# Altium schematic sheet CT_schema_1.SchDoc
size 404 x 338 mm
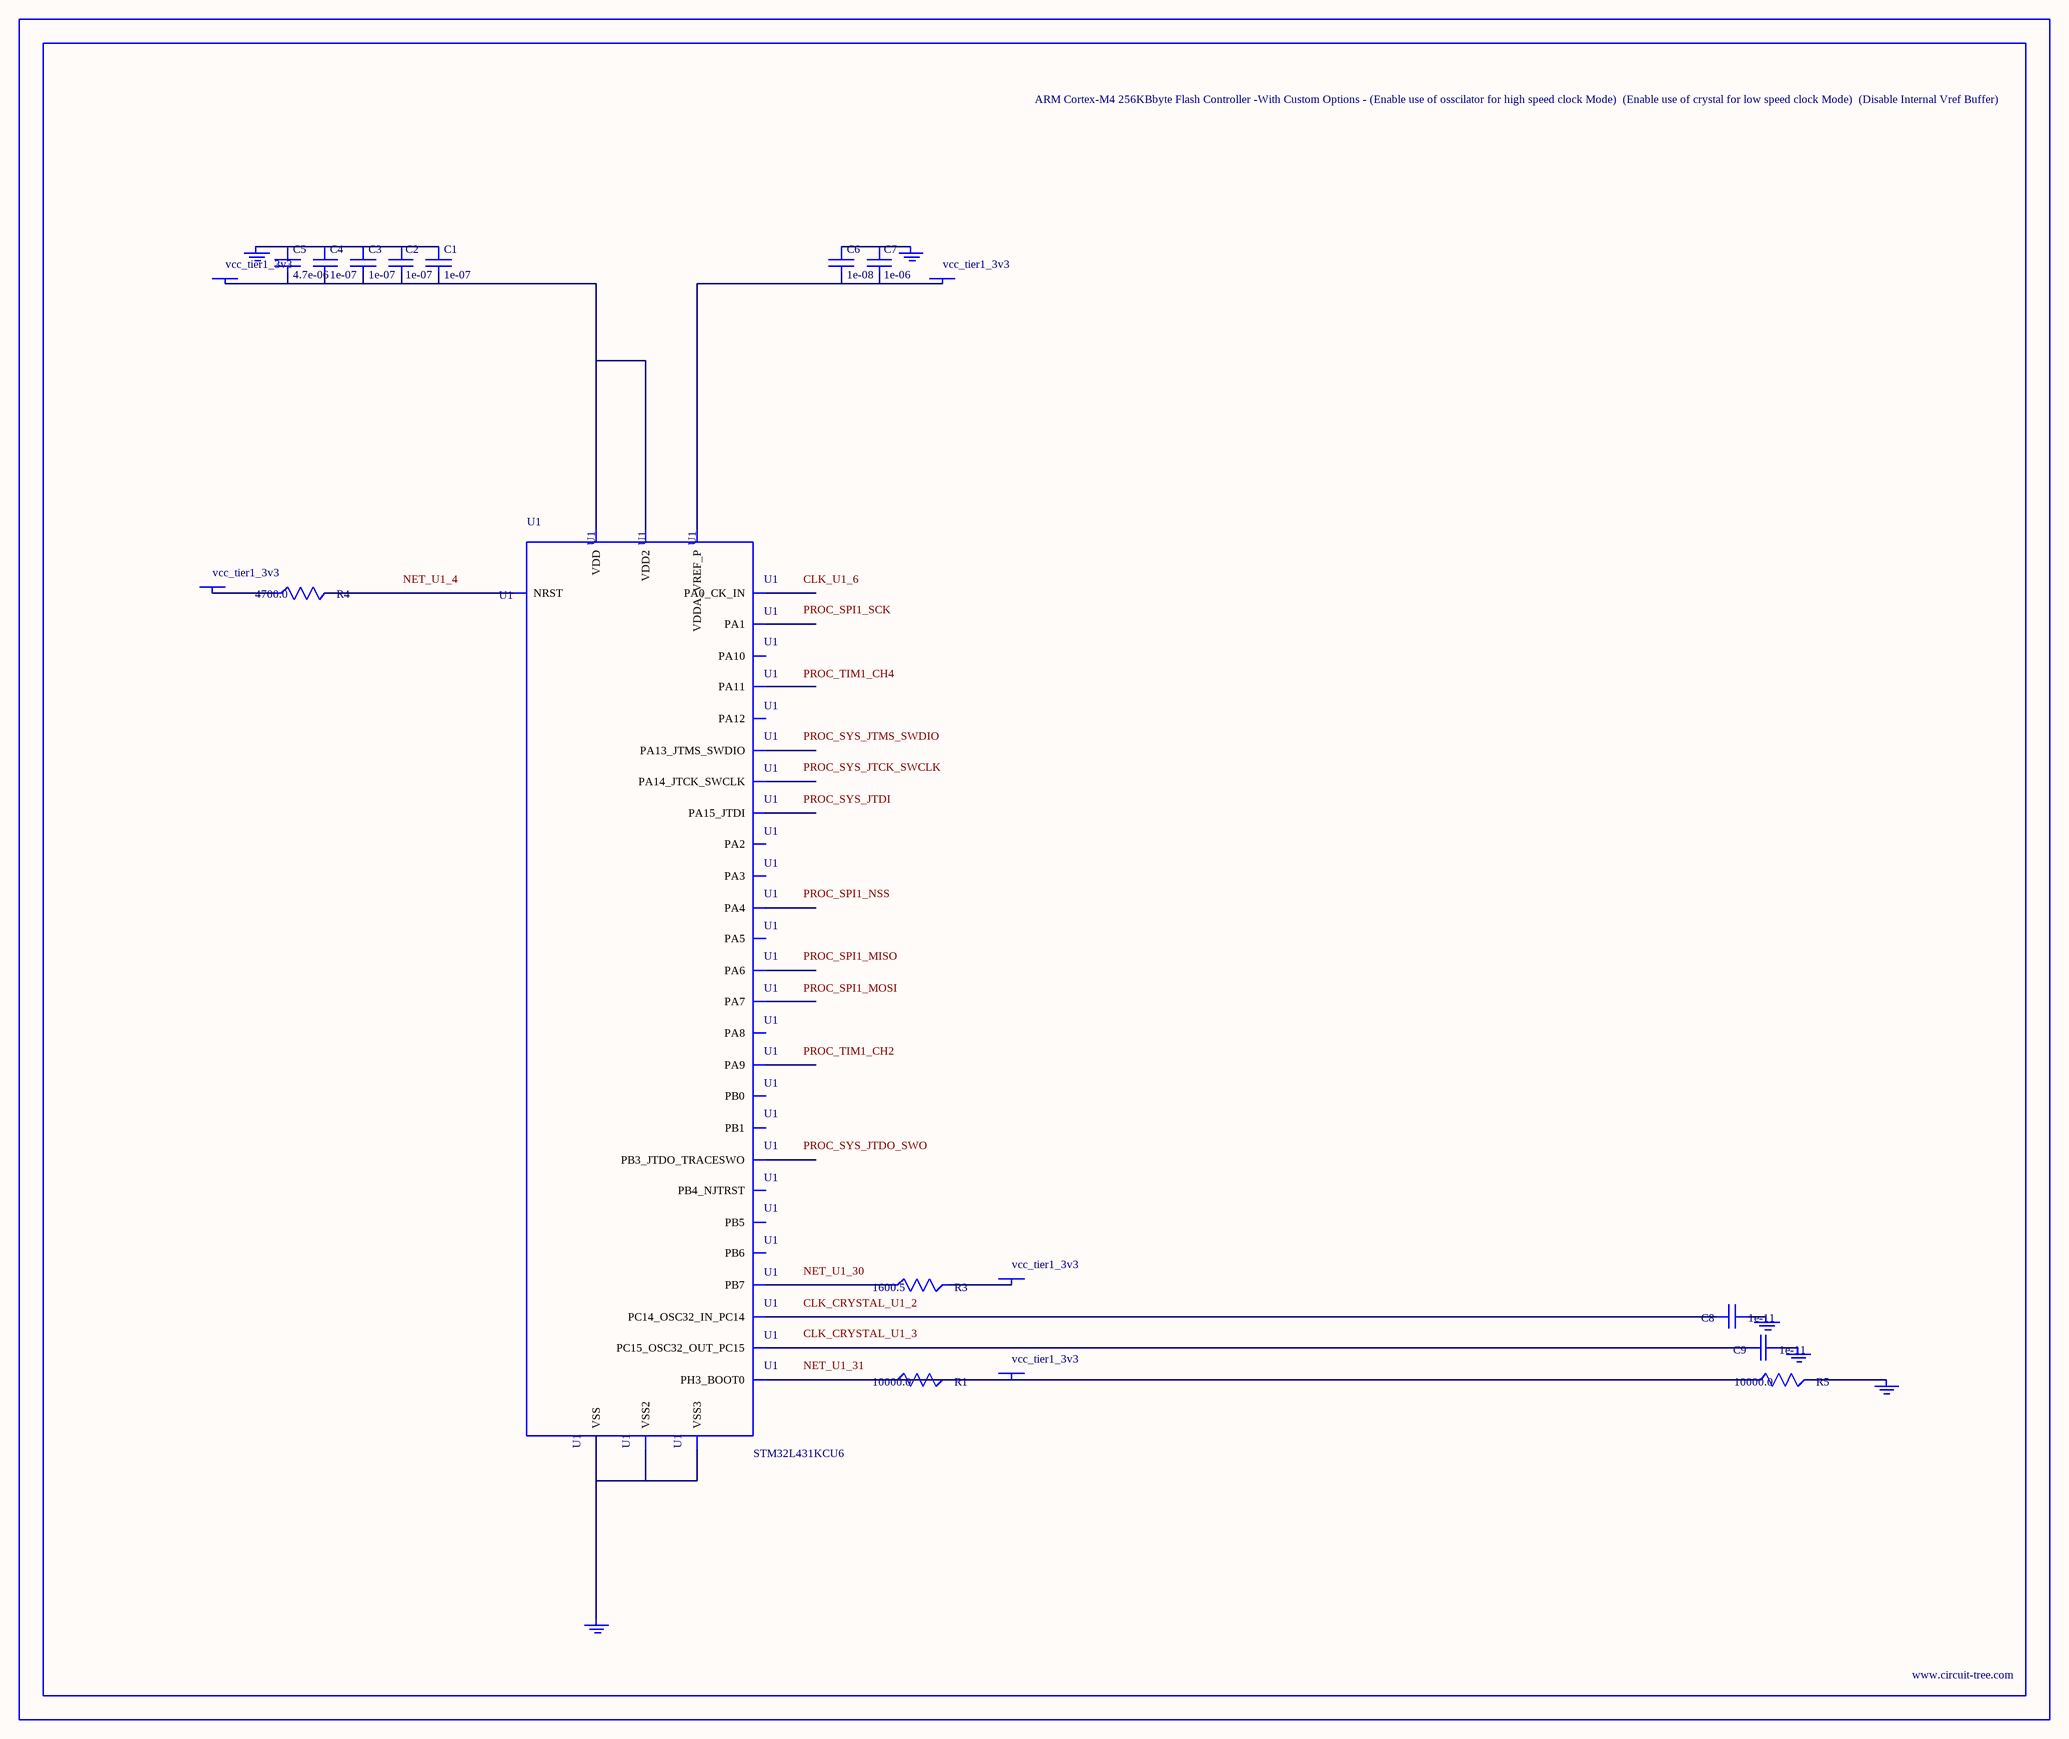
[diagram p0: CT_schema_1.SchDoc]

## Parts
BORDER0  (no value)
C1  1e-07  [C0603]
C2  1e-07  [C0603]
C3  1e-07  [C0603]
C4  1e-07  [C0603]
C5  4.7e-06  [C0603]
C6  1e-08  [C0603]
C7  1e-06  [C0603]
C8  1e-11  [C0402]
C9  1e-11  [C0402]
GND_INSTANCE_0_0  (no value)
GND_INSTANCE_0_1  (no value)
GND_INSTANCE_0_2  (no value)
GND_INSTANCE_0_3  (no value)
GND_INSTANCE_0_4  (no value)
GND_INSTANCE_0_5  (no value)
POWER_INSTANCE_0_0  vcc_tier1_3v3
POWER_INSTANCE_0_1  vcc_tier1_3v3
POWER_INSTANCE_0_2  vcc_tier1_3v3
POWER_INSTANCE_0_3  vcc_tier1_3v3
POWER_INSTANCE_0_4  vcc_tier1_3v3
R1  10000.0  [R0603]
R3  1600.5  [R0603]
R4  4700.0  [R0603]
R5  10000.0  [R0603]
U1  STM32L431KCU6  [QFN-32]

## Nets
NetC1_1: C1.1 C2.1 C3.1 C4.1 C5.1 GND_INSTANCE_0_0.0(GND)
NetC1_2: C1.2 C2.2 C3.2 C4.2 C5.2 POWER_INSTANCE_0_0.0(PWR) U1.1(VDD) U1.17(VDD2)
NetC6_1: C6.1 C7.1 GND_INSTANCE_0_3.0(GND)
NetC6_2: C6.2 C7.2 POWER_INSTANCE_0_1.0(PWR) U1.5(VDDA_VREF_P)
NetC8_1: C8.1 GND_INSTANCE_0_1.0(GND)
NetC8_2: C8.2 U1.2(PC14_OSC32_IN_PC14)
NetC9_1: C9.1 GND_INSTANCE_0_2.0(GND)
NetC9_2: C9.2 U1.3(PC15_OSC32_OUT_PC15)
NetGND_INSTANCE_0_4_0: GND_INSTANCE_0_4.0(GND) R5.2
NetGND_INSTANCE_0_5_0: GND_INSTANCE_0_5.0(GND) U1.16(VSS) U1.32(VSS2) U1.EXP(VSS3)
NetPOWER_INSTANCE_0_2_0: POWER_INSTANCE_0_2.0(PWR) R4.1
NetPOWER_INSTANCE_0_3_0: POWER_INSTANCE_0_3.0(PWR) R3.2
NetPOWER_INSTANCE_0_4_0: POWER_INSTANCE_0_4.0(PWR) R1.1 R1.2 R5.1 U1.31(PH3_BOOT0)
NetR3_1: R3.1 U1.30(PB7)
NetR4_2: R4.2 U1.4(NRST)

Not connected (* = marked no-connect by the designer): U1 6(PA0_CK_IN) 7(PA1) 8(PA2) 9(PA3) 10(PA4) 11(PA5) 12(PA6) 13(PA7) 14(PB0) 15(PB1) 18(PA8) 19(PA9) 20(PA10) 21(PA11) 22(PA12) 23(PA13_JTMS_SWDIO) 24(PA14_JTCK_SWCLK) 25(PA15_JTDI) 26(PB3_JTDO_TRACESWO) 27(PB4_NJTRST) 28(PB5) 29(PB6)

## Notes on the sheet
- Labels drawn without touching a wire or pin: CLK_CRYSTAL_U1_2, CLK_CRYSTAL_U1_3, CLK_U1_6, NET_U1_4, NET_U1_30, NET_U1_31, PROC_SPI1_MISO, PROC_SPI1_MOSI, PROC_SPI1_NSS, PROC_SPI1_SCK, PROC_SYS_JTCK_SWCLK, PROC_SYS_JTDI, PROC_SYS_JTDO_SWO, PROC_SYS_JTMS_SWDIO, PROC_TIM1_CH2, PROC_TIM1_CH4

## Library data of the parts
BORDER0 = BORDER_PAGE0
C1-C4 = 06035C104K4Z2A
C5 = GRM188R6YA475KE15D
C6 = 06035C103K4Z2A
C7 = C0603C105K3RACTU
C8 C9 = C0402C100K3GACTU
GND_INSTANCE_0_0-GND_INSTANCE_0_5 = GND
POWER_INSTANCE_0_0-POWER_INSTANCE_0_4 = PWR
R1 R5 = RC0603JR-0710KL
R3 = R3
R4 = RC0603JR-074K7L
